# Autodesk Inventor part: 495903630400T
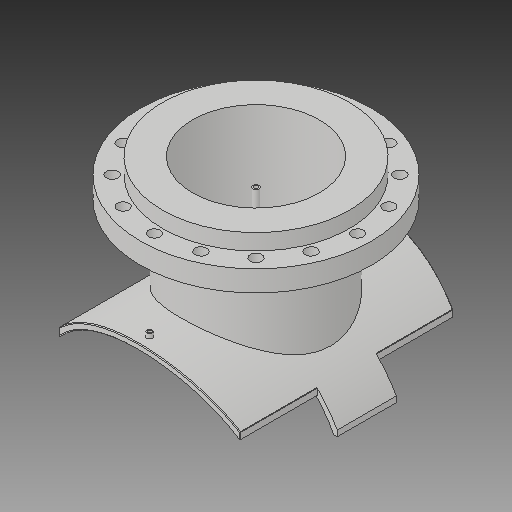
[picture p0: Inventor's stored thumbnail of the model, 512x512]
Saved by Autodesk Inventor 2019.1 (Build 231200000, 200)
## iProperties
Created: 2017-10
Part Number: 495903630400T
Material: Generic
Description: PLASSON FLANGED BRANCH SADDLE 630X400
Document SubType Name: Modeling
Designer: KIM
Mass: 2339.99 g
Surface Area: 3251.55 cm^2
Volume: 2339.99 cm^3
Density: 1 g/cm^3
Appearance: Default
Author: KIM
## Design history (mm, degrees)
derived "495904_495903.ipt"
feature "Solid1::495904_495903.ipt"
feature "Solid2::495904_495903.ipt"
tag "TaggingFeature1"
body "Solid1"
other parameters: "d1" = 15, "d2" = 468, "d4" = 0, "d6" = 152.5, "d7" = 0, "d12" = 340.6, "d13" = 14, "d14" = 274.5, "d16" = 5 deg, "d18" = 4, "d19" = 14, "d20" = 0, "d21" = 3, "d22" = 0, "d36" = 274.5, "d38" = 0, "d39" = 2, "d41" = 327, "d42" = 482, "d43" = 595, "d44" = 224, "d46" = 385.6, "d47" = 16, "d48" = 10.4, "d49" = 196, "d51" = 642.6, "d53" = 0, "d55" = 262.5, "d57" = 0, "d59" = 360 deg, "d61" = 54, "d63" = 0, "d67" = 15, "d70" = 0, "d71" = 2, "d_1" = 482, "x_" = 15, "D_" = 16, "DN_" = 327, "D_1" = 595, "t_" = 54, "Dp_" = 525
